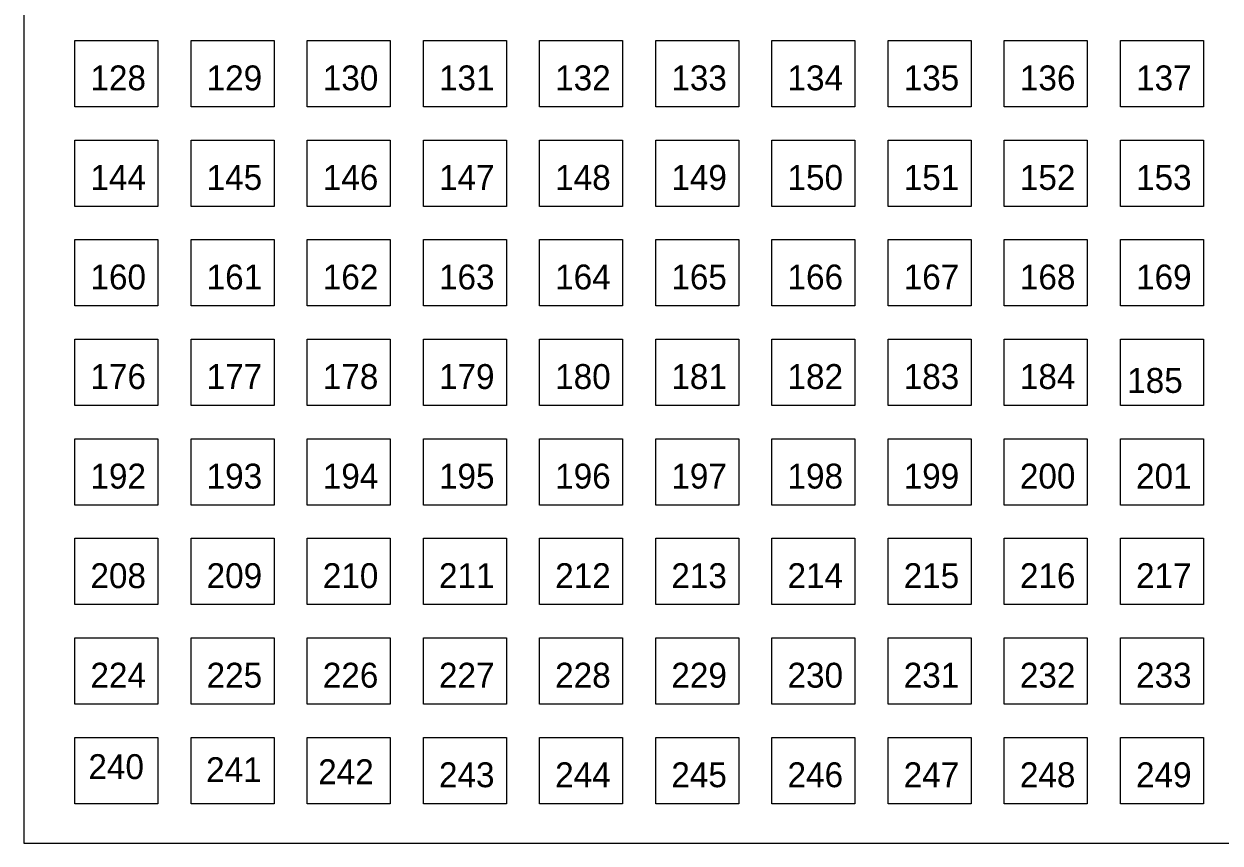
# Model space of a CAD drawing. Extents: x 11193 to 12507, y 10092 to 10555.
# Drawn here: x 11927 to 12215.3, y 10137.6 to 10335 of the extents above; entities that cross this region are included whole.
import ezdxf

# ---------------------------------------------------------------- set-up
doc = ezdxf.new("R2010")
doc.units = 0
for name, color, linetype in [('Level 3', 7, 'Continuous'), ('Level 62', 7, 'Continuous'), ('Level 63', 7, 'Continuous')]:
    doc.layers.add(name, color=color, linetype=linetype)

msp = doc.modelspace()

# ---------------------------------------------------------------- linework, layer by layer
at = {"layer": 'Level 3'}
msp.add_lwpolyline([(11926.98, 10137.56), (12506.98, 10137.56), (12506.98, 10542.56), (11926.98, 10542.56), (11926.98, 10137.56)], dxfattribs=at)
for points in [[(11939.26, 10315.04), (11939.26, 10331.04), (11959.26, 10331.04), (11959.26, 10315.04)], [(11967.26, 10315.04), (11967.26, 10331.04), (11987.26, 10331.04), (11987.26, 10315.04)], [(11995.26, 10315.04), (11995.26, 10331.04), (12015.26, 10331.04), (12015.26, 10315.04)], [(12023.26, 10315.04), (12023.26, 10331.04), (12043.26, 10331.04), (12043.26, 10315.04)], [(12051.26, 10315.04), (12051.26, 10331.04), (12071.26, 10331.04), (12071.26, 10315.04)], [(12079.26, 10315.04), (12079.26, 10331.04), (12099.26, 10331.04), (12099.26, 10315.04)], [(12107.26, 10315.04), (12107.26, 10331.04), (12127.26, 10331.04), (12127.26, 10315.04)], [(12135.26, 10315.04), (12135.26, 10331.04), (12155.26, 10331.04), (12155.26, 10315.04)], [(12163.26, 10315.04), (12163.26, 10331.04), (12183.26, 10331.04), (12183.26, 10315.04)], [(12191.26, 10315.04), (12191.26, 10331.04), (12211.26, 10331.04), (12211.26, 10315.04)], [(11939.26, 10291.04), (11939.26, 10307.04), (11959.26, 10307.04), (11959.26, 10291.04)], [(11967.26, 10291.04), (11967.26, 10307.04), (11987.26, 10307.04), (11987.26, 10291.04)], [(11995.26, 10291.04), (11995.26, 10307.04), (12015.26, 10307.04), (12015.26, 10291.04)], [(12023.26, 10291.04), (12023.26, 10307.04), (12043.26, 10307.04), (12043.26, 10291.04)], [(12051.26, 10291.04), (12051.26, 10307.04), (12071.26, 10307.04), (12071.26, 10291.04)], [(12079.26, 10291.04), (12079.26, 10307.04), (12099.26, 10307.04), (12099.26, 10291.04)], [(12107.26, 10291.04), (12107.26, 10307.04), (12127.26, 10307.04), (12127.26, 10291.04)], [(12135.26, 10291.04), (12135.26, 10307.04), (12155.26, 10307.04), (12155.26, 10291.04)], [(12163.26, 10291.04), (12163.26, 10307.04), (12183.26, 10307.04), (12183.26, 10291.04)], [(12191.26, 10291.04), (12191.26, 10307.04), (12211.26, 10307.04), (12211.26, 10291.04)], [(11939.26, 10267.04), (11939.26, 10283.04), (11959.26, 10283.04), (11959.26, 10267.04)], [(11967.26, 10267.04), (11967.26, 10283.04), (11987.26, 10283.04), (11987.26, 10267.04)], [(11995.26, 10267.04), (11995.26, 10283.04), (12015.26, 10283.04), (12015.26, 10267.04)], [(12023.26, 10267.04), (12023.26, 10283.04), (12043.26, 10283.04), (12043.26, 10267.04)], [(12051.26, 10267.04), (12051.26, 10283.04), (12071.26, 10283.04), (12071.26, 10267.04)], [(12079.26, 10267.04), (12079.26, 10283.04), (12099.26, 10283.04), (12099.26, 10267.04)], [(12107.26, 10267.04), (12107.26, 10283.04), (12127.26, 10283.04), (12127.26, 10267.04)], [(12135.26, 10267.04), (12135.26, 10283.04), (12155.26, 10283.04), (12155.26, 10267.04)], [(12163.26, 10267.04), (12163.26, 10283.04), (12183.26, 10283.04), (12183.26, 10267.04)], [(12191.26, 10267.04), (12191.26, 10283.04), (12211.26, 10283.04), (12211.26, 10267.04)], [(11939.26, 10243.04), (11939.26, 10259.04), (11959.26, 10259.04), (11959.26, 10243.04)], [(11967.26, 10243.04), (11967.26, 10259.04), (11987.26, 10259.04), (11987.26, 10243.04)], [(11995.26, 10243.04), (11995.26, 10259.04), (12015.26, 10259.04), (12015.26, 10243.04)], [(12023.26, 10243.04), (12023.26, 10259.04), (12043.26, 10259.04), (12043.26, 10243.04)], [(12051.26, 10243.04), (12051.26, 10259.04), (12071.26, 10259.04), (12071.26, 10243.04)], [(12079.26, 10243.04), (12079.26, 10259.04), (12099.26, 10259.04), (12099.26, 10243.04)], [(12107.26, 10243.04), (12107.26, 10259.04), (12127.26, 10259.04), (12127.26, 10243.04)], [(12135.26, 10243.04), (12135.26, 10259.04), (12155.26, 10259.04), (12155.26, 10243.04)], [(12163.26, 10243.04), (12163.26, 10259.04), (12183.26, 10259.04), (12183.26, 10243.04)], [(12191.26, 10243.04), (12191.26, 10259.04), (12211.26, 10259.04), (12211.26, 10243.04)], [(11939.26, 10219.04), (11939.26, 10235.04), (11959.26, 10235.04), (11959.26, 10219.04)], [(11967.26, 10219.04), (11967.26, 10235.04), (11987.26, 10235.04), (11987.26, 10219.04)], [(11995.26, 10219.04), (11995.26, 10235.04), (12015.26, 10235.04), (12015.26, 10219.04)], [(12023.26, 10219.04), (12023.26, 10235.04), (12043.26, 10235.04), (12043.26, 10219.04)], [(12051.26, 10219.04), (12051.26, 10235.04), (12071.26, 10235.04), (12071.26, 10219.04)], [(12079.26, 10219.04), (12079.26, 10235.04), (12099.26, 10235.04), (12099.26, 10219.04)], [(12107.26, 10219.04), (12107.26, 10235.04), (12127.26, 10235.04), (12127.26, 10219.04)], [(12135.26, 10219.04), (12135.26, 10235.04), (12155.26, 10235.04), (12155.26, 10219.04)], [(12163.26, 10219.04), (12163.26, 10235.04), (12183.26, 10235.04), (12183.26, 10219.04)], [(12191.26, 10219.04), (12191.26, 10235.04), (12211.26, 10235.04), (12211.26, 10219.04)], [(11939.26, 10195.04), (11939.26, 10211.04), (11959.26, 10211.04), (11959.26, 10195.04)], [(11967.26, 10195.04), (11967.26, 10211.04), (11987.26, 10211.04), (11987.26, 10195.04)], [(11995.26, 10195.04), (11995.26, 10211.04), (12015.26, 10211.04), (12015.26, 10195.04)], [(12023.26, 10195.04), (12023.26, 10211.04), (12043.26, 10211.04), (12043.26, 10195.04)], [(12051.26, 10195.04), (12051.26, 10211.04), (12071.26, 10211.04), (12071.26, 10195.04)], [(12079.26, 10195.04), (12079.26, 10211.04), (12099.26, 10211.04), (12099.26, 10195.04)], [(12107.26, 10195.04), (12107.26, 10211.04), (12127.26, 10211.04), (12127.26, 10195.04)], [(12135.26, 10195.04), (12135.26, 10211.04), (12155.26, 10211.04), (12155.26, 10195.04)], [(12163.26, 10195.04), (12163.26, 10211.04), (12183.26, 10211.04), (12183.26, 10195.04)], [(12191.26, 10195.04), (12191.26, 10211.04), (12211.26, 10211.04), (12211.26, 10195.04)], [(11939.26, 10171.04), (11939.26, 10187.04), (11959.26, 10187.04), (11959.26, 10171.04)], [(11967.26, 10171.04), (11967.26, 10187.04), (11987.26, 10187.04), (11987.26, 10171.04)], [(11995.26, 10171.04), (11995.26, 10187.04), (12015.26, 10187.04), (12015.26, 10171.04)], [(12023.26, 10171.04), (12023.26, 10187.04), (12043.26, 10187.04), (12043.26, 10171.04)], [(12051.26, 10171.04), (12051.26, 10187.04), (12071.26, 10187.04), (12071.26, 10171.04)], [(12079.26, 10171.04), (12079.26, 10187.04), (12099.26, 10187.04), (12099.26, 10171.04)], [(12107.26, 10171.04), (12107.26, 10187.04), (12127.26, 10187.04), (12127.26, 10171.04)], [(12135.26, 10171.04), (12135.26, 10187.04), (12155.26, 10187.04), (12155.26, 10171.04)], [(12163.26, 10171.04), (12163.26, 10187.04), (12183.26, 10187.04), (12183.26, 10171.04)], [(12191.26, 10171.04), (12191.26, 10187.04), (12211.26, 10187.04), (12211.26, 10171.04)], [(11939.26, 10147.04), (11939.26, 10163.04), (11959.26, 10163.04), (11959.26, 10147.04)], [(11967.26, 10147.04), (11967.26, 10163.04), (11987.26, 10163.04), (11987.26, 10147.04)], [(11995.26, 10147.04), (11995.26, 10163.04), (12015.26, 10163.04), (12015.26, 10147.04)], [(12023.26, 10147.04), (12023.26, 10163.04), (12043.26, 10163.04), (12043.26, 10147.04)], [(12051.26, 10147.04), (12051.26, 10163.04), (12071.26, 10163.04), (12071.26, 10147.04)], [(12079.26, 10147.04), (12079.26, 10163.04), (12099.26, 10163.04), (12099.26, 10147.04)], [(12107.26, 10147.04), (12107.26, 10163.04), (12127.26, 10163.04), (12127.26, 10147.04)], [(12135.26, 10147.04), (12135.26, 10163.04), (12155.26, 10163.04), (12155.26, 10147.04)], [(12163.26, 10147.04), (12163.26, 10163.04), (12183.26, 10163.04), (12183.26, 10147.04)], [(12191.26, 10147.04), (12191.26, 10163.04), (12211.26, 10163.04), (12211.26, 10147.04)]]:
    msp.add_lwpolyline(points, close=True, dxfattribs=at)
at = {"layer": 'Level 63'}
for points in [[(11939.26, 10315.04), (11939.26, 10331.04), (11959.26, 10331.04), (11959.26, 10315.04)], [(11967.26, 10315.04), (11967.26, 10331.04), (11987.26, 10331.04), (11987.26, 10315.04)], [(11995.26, 10315.04), (11995.26, 10331.04), (12015.26, 10331.04), (12015.26, 10315.04)], [(12023.26, 10315.04), (12023.26, 10331.04), (12043.26, 10331.04), (12043.26, 10315.04)], [(12051.26, 10315.04), (12051.26, 10331.04), (12071.26, 10331.04), (12071.26, 10315.04)], [(12079.26, 10315.04), (12079.26, 10331.04), (12099.26, 10331.04), (12099.26, 10315.04)], [(12107.26, 10315.04), (12107.26, 10331.04), (12127.26, 10331.04), (12127.26, 10315.04)], [(12135.26, 10315.04), (12135.26, 10331.04), (12155.26, 10331.04), (12155.26, 10315.04)], [(12163.26, 10315.04), (12163.26, 10331.04), (12183.26, 10331.04), (12183.26, 10315.04)], [(12191.26, 10315.04), (12191.26, 10331.04), (12211.26, 10331.04), (12211.26, 10315.04)], [(11939.26, 10291.04), (11939.26, 10307.04), (11959.26, 10307.04), (11959.26, 10291.04)], [(11967.26, 10291.04), (11967.26, 10307.04), (11987.26, 10307.04), (11987.26, 10291.04)], [(11995.26, 10291.04), (11995.26, 10307.04), (12015.26, 10307.04), (12015.26, 10291.04)], [(12023.26, 10291.04), (12023.26, 10307.04), (12043.26, 10307.04), (12043.26, 10291.04)], [(12051.26, 10291.04), (12051.26, 10307.04), (12071.26, 10307.04), (12071.26, 10291.04)], [(12079.26, 10291.04), (12079.26, 10307.04), (12099.26, 10307.04), (12099.26, 10291.04)], [(12107.26, 10291.04), (12107.26, 10307.04), (12127.26, 10307.04), (12127.26, 10291.04)], [(12135.26, 10291.04), (12135.26, 10307.04), (12155.26, 10307.04), (12155.26, 10291.04)], [(12163.26, 10291.04), (12163.26, 10307.04), (12183.26, 10307.04), (12183.26, 10291.04)], [(12191.26, 10291.04), (12191.26, 10307.04), (12211.26, 10307.04), (12211.26, 10291.04)], [(11939.26, 10267.04), (11939.26, 10283.04), (11959.26, 10283.04), (11959.26, 10267.04)], [(11967.26, 10267.04), (11967.26, 10283.04), (11987.26, 10283.04), (11987.26, 10267.04)], [(11995.26, 10267.04), (11995.26, 10283.04), (12015.26, 10283.04), (12015.26, 10267.04)], [(12023.26, 10267.04), (12023.26, 10283.04), (12043.26, 10283.04), (12043.26, 10267.04)], [(12051.26, 10267.04), (12051.26, 10283.04), (12071.26, 10283.04), (12071.26, 10267.04)], [(12079.26, 10267.04), (12079.26, 10283.04), (12099.26, 10283.04), (12099.26, 10267.04)], [(12107.26, 10267.04), (12107.26, 10283.04), (12127.26, 10283.04), (12127.26, 10267.04)], [(12135.26, 10267.04), (12135.26, 10283.04), (12155.26, 10283.04), (12155.26, 10267.04)], [(12163.26, 10267.04), (12163.26, 10283.04), (12183.26, 10283.04), (12183.26, 10267.04)], [(12191.26, 10267.04), (12191.26, 10283.04), (12211.26, 10283.04), (12211.26, 10267.04)], [(11939.26, 10243.04), (11939.26, 10259.04), (11959.26, 10259.04), (11959.26, 10243.04)], [(11967.26, 10243.04), (11967.26, 10259.04), (11987.26, 10259.04), (11987.26, 10243.04)], [(11995.26, 10243.04), (11995.26, 10259.04), (12015.26, 10259.04), (12015.26, 10243.04)], [(12023.26, 10243.04), (12023.26, 10259.04), (12043.26, 10259.04), (12043.26, 10243.04)], [(12051.26, 10243.04), (12051.26, 10259.04), (12071.26, 10259.04), (12071.26, 10243.04)], [(12079.26, 10243.04), (12079.26, 10259.04), (12099.26, 10259.04), (12099.26, 10243.04)], [(12107.26, 10243.04), (12107.26, 10259.04), (12127.26, 10259.04), (12127.26, 10243.04)], [(12135.26, 10243.04), (12135.26, 10259.04), (12155.26, 10259.04), (12155.26, 10243.04)], [(12163.26, 10243.04), (12163.26, 10259.04), (12183.26, 10259.04), (12183.26, 10243.04)], [(12191.26, 10243.04), (12191.26, 10259.04), (12211.26, 10259.04), (12211.26, 10243.04)], [(11939.26, 10219.04), (11939.26, 10235.04), (11959.26, 10235.04), (11959.26, 10219.04)], [(11967.26, 10219.04), (11967.26, 10235.04), (11987.26, 10235.04), (11987.26, 10219.04)], [(11995.26, 10219.04), (11995.26, 10235.04), (12015.26, 10235.04), (12015.26, 10219.04)], [(12023.26, 10219.04), (12023.26, 10235.04), (12043.26, 10235.04), (12043.26, 10219.04)], [(12051.26, 10219.04), (12051.26, 10235.04), (12071.26, 10235.04), (12071.26, 10219.04)], [(12079.26, 10219.04), (12079.26, 10235.04), (12099.26, 10235.04), (12099.26, 10219.04)], [(12107.26, 10219.04), (12107.26, 10235.04), (12127.26, 10235.04), (12127.26, 10219.04)], [(12135.26, 10219.04), (12135.26, 10235.04), (12155.26, 10235.04), (12155.26, 10219.04)], [(12163.26, 10219.04), (12163.26, 10235.04), (12183.26, 10235.04), (12183.26, 10219.04)], [(12191.26, 10219.04), (12191.26, 10235.04), (12211.26, 10235.04), (12211.26, 10219.04)], [(11939.26, 10195.04), (11939.26, 10211.04), (11959.26, 10211.04), (11959.26, 10195.04)], [(11967.26, 10195.04), (11967.26, 10211.04), (11987.26, 10211.04), (11987.26, 10195.04)], [(11995.26, 10195.04), (11995.26, 10211.04), (12015.26, 10211.04), (12015.26, 10195.04)], [(12023.26, 10195.04), (12023.26, 10211.04), (12043.26, 10211.04), (12043.26, 10195.04)], [(12051.26, 10195.04), (12051.26, 10211.04), (12071.26, 10211.04), (12071.26, 10195.04)], [(12079.26, 10195.04), (12079.26, 10211.04), (12099.26, 10211.04), (12099.26, 10195.04)], [(12107.26, 10195.04), (12107.26, 10211.04), (12127.26, 10211.04), (12127.26, 10195.04)], [(12135.26, 10195.04), (12135.26, 10211.04), (12155.26, 10211.04), (12155.26, 10195.04)], [(12163.26, 10195.04), (12163.26, 10211.04), (12183.26, 10211.04), (12183.26, 10195.04)], [(12191.26, 10195.04), (12191.26, 10211.04), (12211.26, 10211.04), (12211.26, 10195.04)], [(11939.26, 10171.04), (11939.26, 10187.04), (11959.26, 10187.04), (11959.26, 10171.04)], [(11967.26, 10171.04), (11967.26, 10187.04), (11987.26, 10187.04), (11987.26, 10171.04)], [(11995.26, 10171.04), (11995.26, 10187.04), (12015.26, 10187.04), (12015.26, 10171.04)], [(12023.26, 10171.04), (12023.26, 10187.04), (12043.26, 10187.04), (12043.26, 10171.04)], [(12051.26, 10171.04), (12051.26, 10187.04), (12071.26, 10187.04), (12071.26, 10171.04)], [(12079.26, 10171.04), (12079.26, 10187.04), (12099.26, 10187.04), (12099.26, 10171.04)], [(12107.26, 10171.04), (12107.26, 10187.04), (12127.26, 10187.04), (12127.26, 10171.04)], [(12135.26, 10171.04), (12135.26, 10187.04), (12155.26, 10187.04), (12155.26, 10171.04)], [(12163.26, 10171.04), (12163.26, 10187.04), (12183.26, 10187.04), (12183.26, 10171.04)], [(12191.26, 10171.04), (12191.26, 10187.04), (12211.26, 10187.04), (12211.26, 10171.04)], [(11939.26, 10147.04), (11939.26, 10163.04), (11959.26, 10163.04), (11959.26, 10147.04)], [(11967.26, 10147.04), (11967.26, 10163.04), (11987.26, 10163.04), (11987.26, 10147.04)], [(11995.26, 10147.04), (11995.26, 10163.04), (12015.26, 10163.04), (12015.26, 10147.04)], [(12023.26, 10147.04), (12023.26, 10163.04), (12043.26, 10163.04), (12043.26, 10147.04)], [(12051.26, 10147.04), (12051.26, 10163.04), (12071.26, 10163.04), (12071.26, 10147.04)], [(12079.26, 10147.04), (12079.26, 10163.04), (12099.26, 10163.04), (12099.26, 10147.04)], [(12107.26, 10147.04), (12107.26, 10163.04), (12127.26, 10163.04), (12127.26, 10147.04)], [(12135.26, 10147.04), (12135.26, 10163.04), (12155.26, 10163.04), (12155.26, 10147.04)], [(12163.26, 10147.04), (12163.26, 10163.04), (12183.26, 10163.04), (12183.26, 10147.04)], [(12191.26, 10147.04), (12191.26, 10163.04), (12211.26, 10163.04), (12211.26, 10147.04)]]:
    msp.add_lwpolyline(points, close=True, dxfattribs=at)

# ---------------------------------------------------------------- texts
at = {"layer": 'Level 62'}
for s, p in [('128', (11943.01, 10319.03)), ('129', (11971.01, 10319.03)), ('130', (11999.01, 10319.03)), ('131', (12027.01, 10319.03)), ('132', (12055.01, 10319.03)), ('133', (12083.01, 10319.03)), ('134', (12111.01, 10319.03)), ('135', (12139.01, 10319.03)), ('136', (12167.01, 10319.03)), ('137', (12195.01, 10319.03)), ('144', (11943.01, 10295.03)), ('145', (11971.01, 10295.03)), ('146', (11999.01, 10295.03)), ('147', (12027.01, 10295.03)), ('148', (12055.01, 10295.03)), ('149', (12083.01, 10295.03)), ('150', (12111.01, 10295.03)), ('151', (12139.01, 10295.03)), ('152', (12167.01, 10295.03)), ('153', (12195.01, 10295.03)), ('160', (11943.01, 10271.03)), ('161', (11971.01, 10271.03)), ('162', (11999.01, 10271.03)), ('163', (12027.01, 10271.03)), ('164', (12055.01, 10271.03)), ('165', (12083.01, 10271.03)), ('166', (12111.01, 10271.03)), ('167', (12139.01, 10271.03)), ('168', (12167.01, 10271.03)), ('169', (12195.01, 10271.03)), ('176', (11943.01, 10247.03)), ('177', (11971.01, 10247.03)), ('178', (11999.01, 10247.03)), ('179', (12027.01, 10247.03)), ('180', (12055.01, 10247.03)), ('181', (12083.01, 10247.03)), ('182', (12111.01, 10247.03)), ('183', (12139.01, 10247.03)), ('184', (12167.01, 10247.03)), ('185', (12192.88, 10246.09)), ('192', (11943.01, 10223.03)), ('193', (11971.01, 10223.03)), ('194', (11999.01, 10223.03)), ('195', (12027.01, 10223.03)), ('196', (12055.01, 10223.03)), ('197', (12083.01, 10223.03)), ('198', (12111.01, 10223.03)), ('199', (12139.01, 10223.03)), ('200', (12167.01, 10223.03)), ('201', (12195.01, 10223.03)), ('208', (11943.01, 10199.03)), ('209', (11971.01, 10199.03)), ('210', (11999.01, 10199.03)), ('211', (12027.01, 10199.03)), ('212', (12055.01, 10199.03)), ('213', (12083.01, 10199.03)), ('214', (12111.01, 10199.03)), ('215', (12139.01, 10199.03)), ('216', (12167.01, 10199.03)), ('217', (12195.01, 10199.03)), ('224', (11943.01, 10175.03)), ('225', (11971.01, 10175.03)), ('226', (11999.01, 10175.03)), ('227', (12027.01, 10175.03)), ('228', (12055.01, 10175.03)), ('229', (12083.01, 10175.03)), ('230', (12111.01, 10175.03)), ('231', (12139.01, 10175.03)), ('232', (12167.01, 10175.03)), ('233', (12195.01, 10175.03)), ('240', (11942.52, 10152.99)), ('241', (11970.89, 10152.26)), ('242', (11997.9, 10151.76)), ('243', (12027.01, 10151.03)), ('244', (12055.01, 10151.03)), ('245', (12083.01, 10151.03)), ('246', (12111.01, 10151.03)), ('247', (12139.01, 10151.03)), ('248', (12167.01, 10151.03)), ('249', (12195.01, 10151.03))]:
    msp.add_text(s, height=6, dxfattribs=at).set_placement(p)

doc.saveas('drawing.dxf')
